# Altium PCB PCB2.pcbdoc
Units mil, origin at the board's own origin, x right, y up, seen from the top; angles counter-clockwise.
Board outline 2219.76 x 1776.53 mil, 4 copper layers (Top Layer, GND, VCC, Bottom Layer), stack 62.447 mil thick; 53 components, 34 nets, 195 pads, 28 vias.
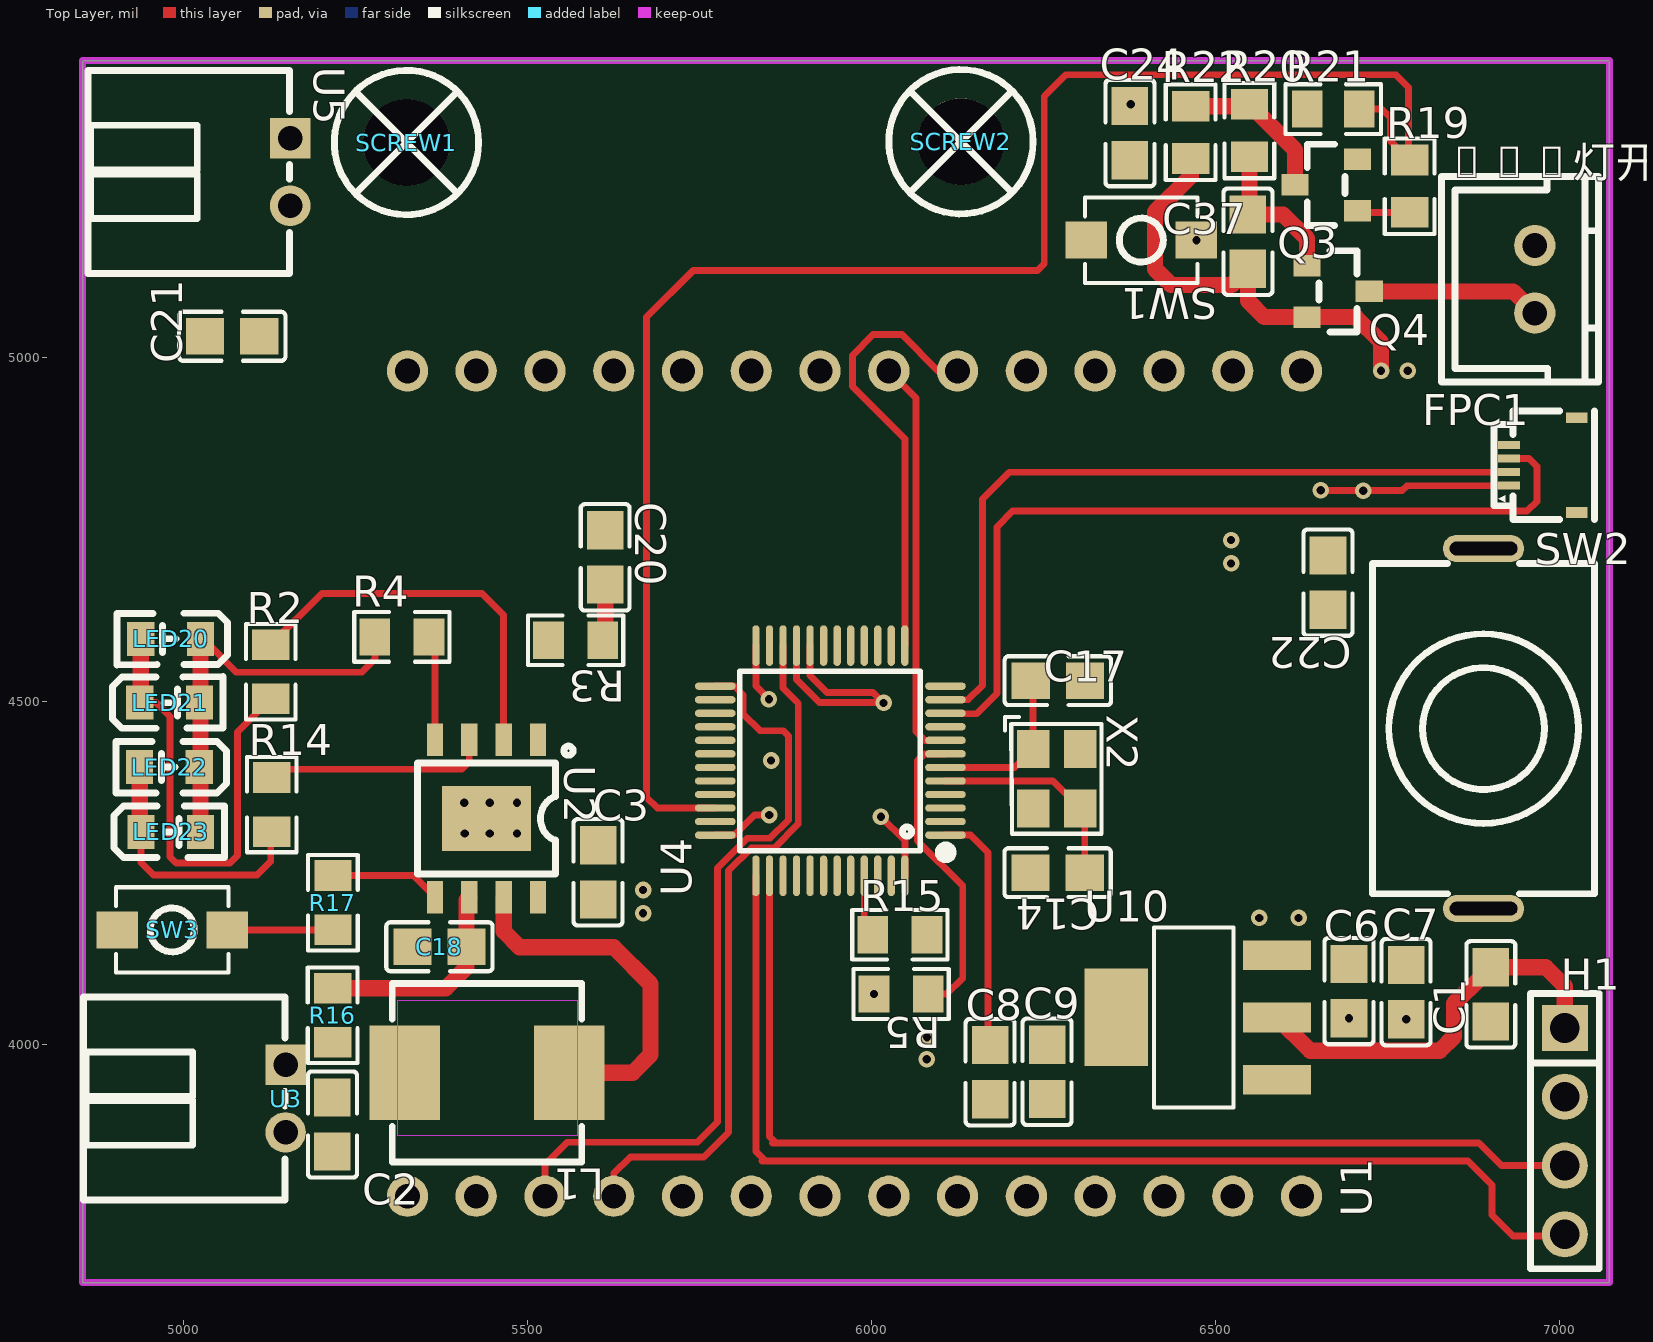
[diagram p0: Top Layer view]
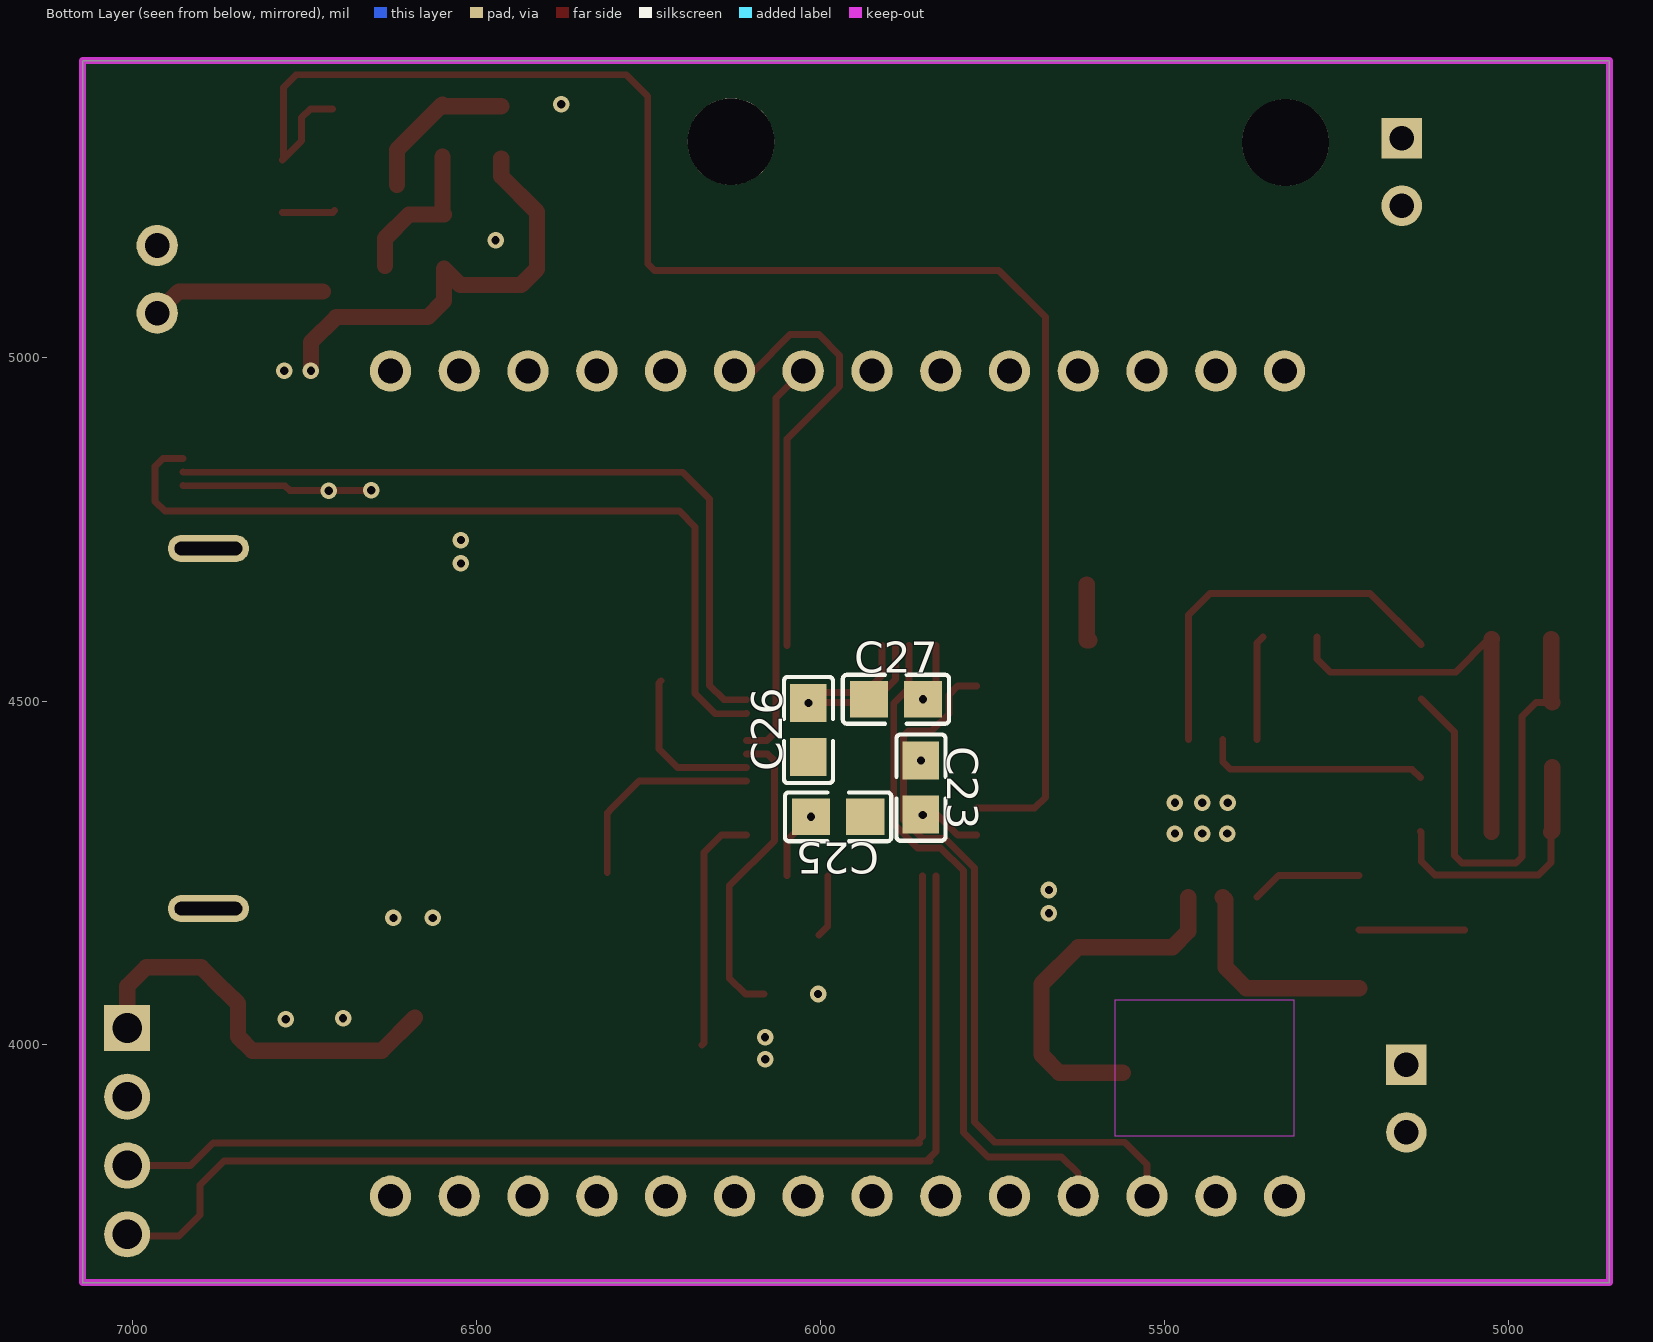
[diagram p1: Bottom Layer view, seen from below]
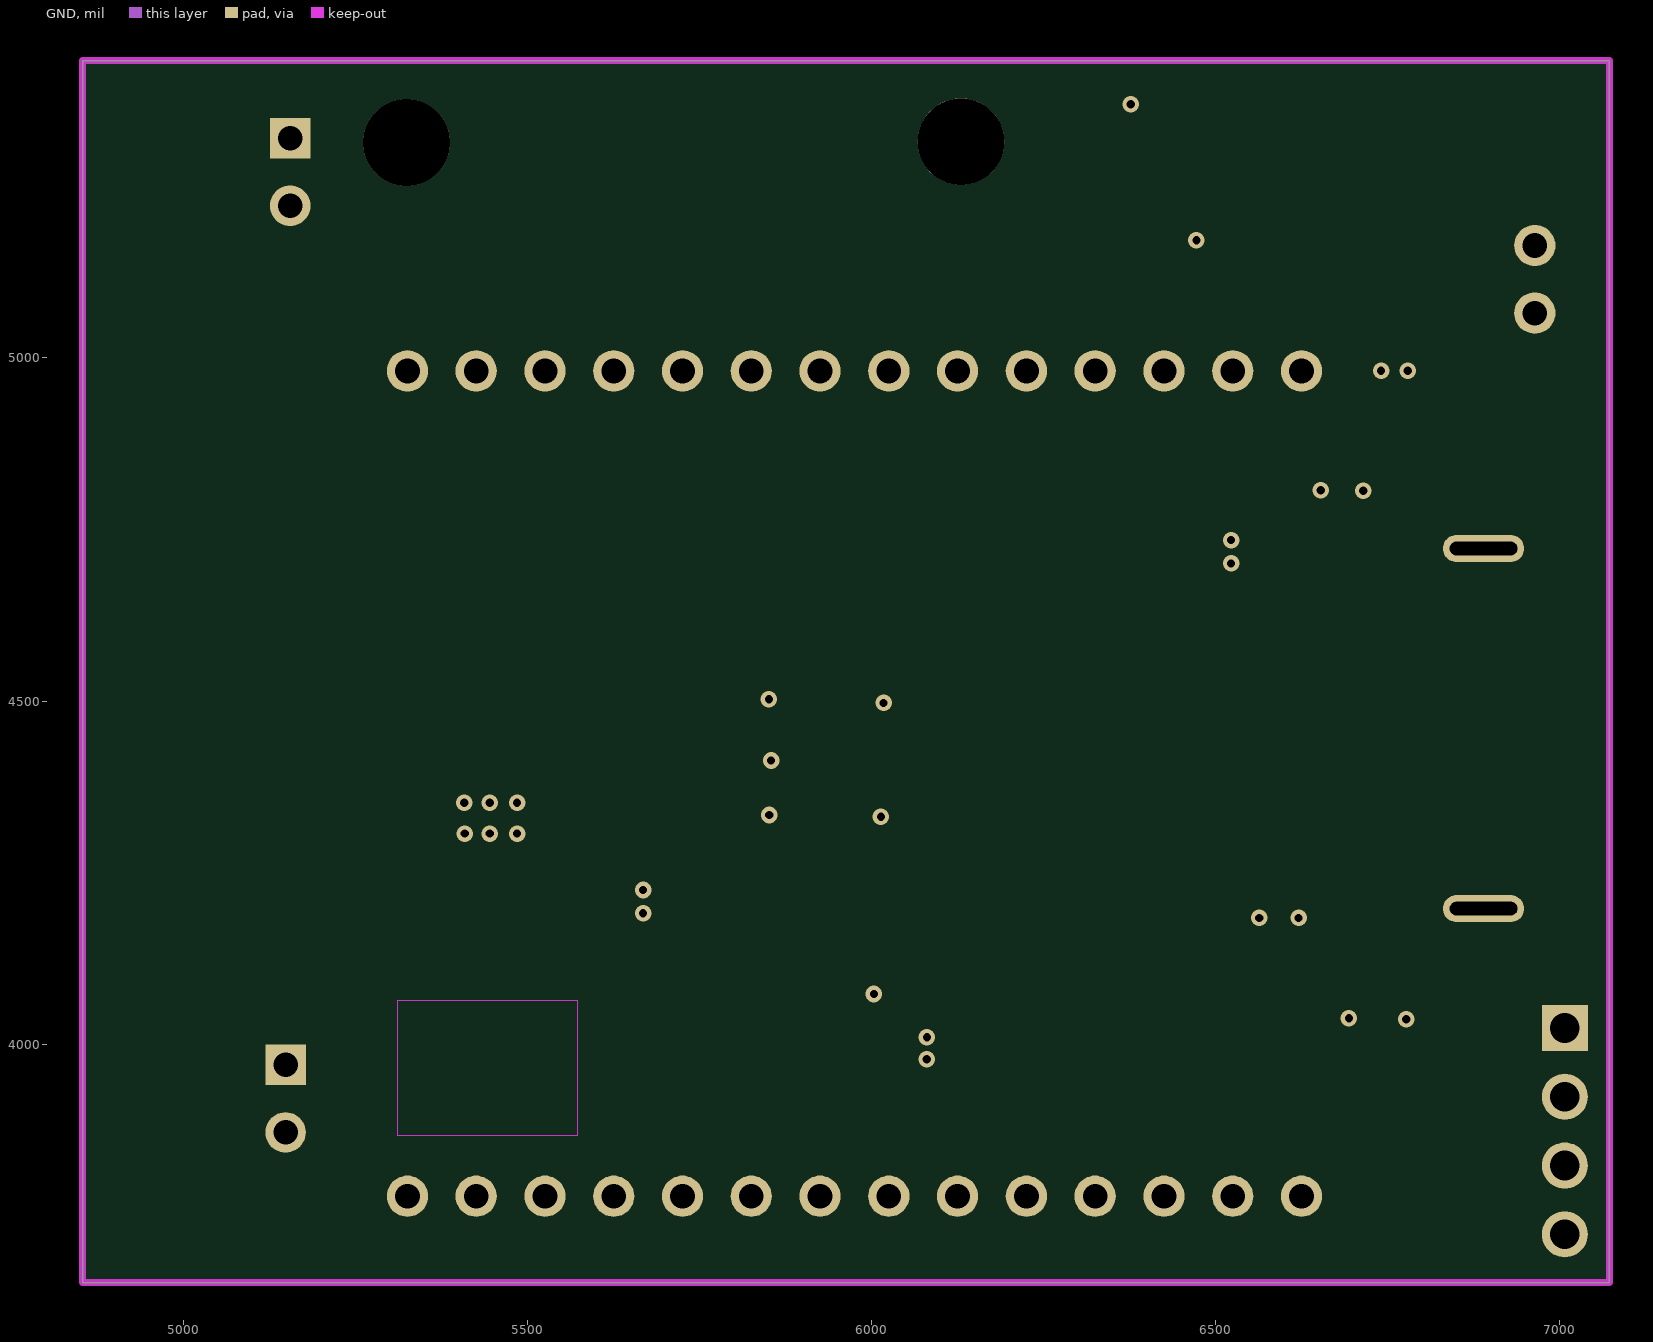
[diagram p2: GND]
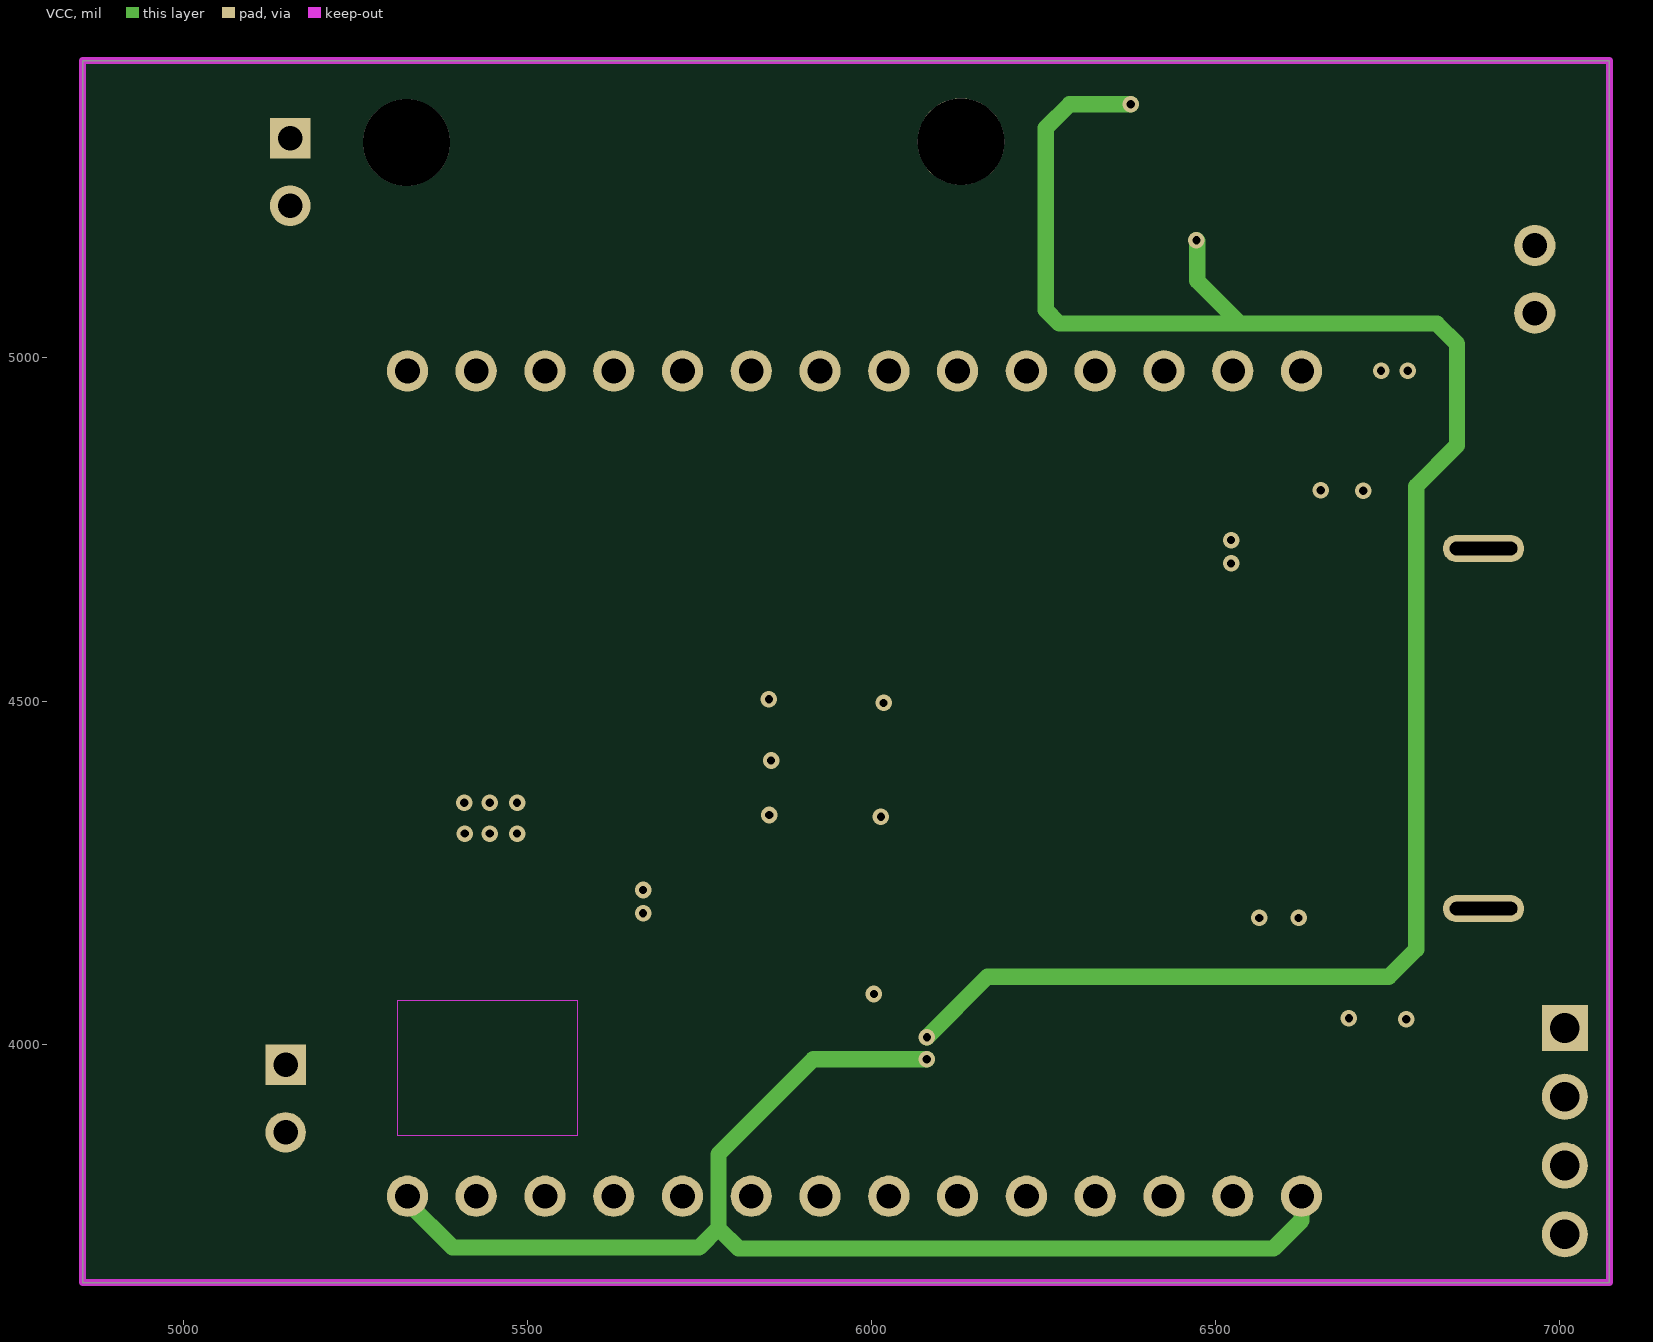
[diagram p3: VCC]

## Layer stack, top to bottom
Top Layer: signal copper 1.378
Dielectric1: surface 8.283, 7628 RC49% 8.6mil, Dk 0
GND: signal copper 0.598
Dielectric2: surface 41.929, 1.1mm H/HOZ Copper, Dk 0
VCC: signal copper 0.598
Dielectric3: surface 8.283, 7628 RC49% 8.6mil, Dk 0
Bottom Layer: signal copper 1.378

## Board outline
4852.85,5431.05 7072.61,5431.05 7072.61,3654.52 4852.85,3654.52

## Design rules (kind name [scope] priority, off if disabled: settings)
BoardOutlineClearance copperThickness1oz [All] p0: genericclearance=10 ignorepadtopadclearanceinfootprint=FALSE except(0: Arc-SplitContinuation Track-SplitContinuation SMDPad-SplitContinuation THPad-SplitContinuation Via-SplitContinuation Fill-SplitContinuation Poly-SplitContinuation Region-SplitContinuation Text-SplitContinuation)
BoardOutlineClearance copperThickness2oz [All] p0: genericclearance=10 ignorepadtopadclearanceinfootprint=FALSE except(0: Arc-SplitContinuation Track-SplitContinuation SMDPad-SplitContinuation THPad-SplitContinuation Via-SplitContinuation Fill-SplitContinuation Poly-SplitContinuation Region-SplitContinuation Text-SplitContinuation)
BoardOutlineClearance otherClearance [All] p0: genericclearance=10 ignorepadtopadclearanceinfootprint=FALSE except(0: Arc-SplitContinuation Track-SplitContinuation SMDPad-SplitContinuation THPad-SplitContinuation Via-SplitContinuation Fill-SplitContinuation Poly-SplitContinuation Region-SplitContinuation Text-SplitContinuation)
Clearance copperThickness1oz [All] p1: gap=7 ignorepadtopadclearanceinfootprint=FALSE
Clearance copperThickness2oz [All] p1: gap=7 ignorepadtopadclearanceinfootprint=FALSE
Clearance otherClearance [All] p1: gap=7 ignorepadtopadclearanceinfootprint=FALSE
DiffPairsRouting differentialPair [All] p1: maxuncoupledlength=10 minlimit=6 maxlimit=Infinity mostfreqgap=6 toplayer_minwidth=5 toplayer_prefwidth=10 toplayer_maxwidth=100 bottomlayer_minwidth=5 bottomlayer_prefwidth=10 bottomlayer_maxwidth=100 midlayer1_minwidth=5 midlayer1_prefwidth=10 midlayer1_maxwidth=100 midlayer2_minwidth=5 midlayer2_prefwidth=10 midlayer2_maxwidth=100
PasteMaskExpansion pasteMaskExpansion [All] p1: expansion=0
PlaneConnect innerPlane [All] p1: planeconnectstyle=Relief reliefexpansion=20 reliefentries=4 reliefconductorwidth=10 reliefairgap=10
PolygonConnect copperRegion [All] p1: connectstyle=Direct reliefentries=4 reliefconductorwidth=10 polygonreliefangle="90 Angle" airgapwidth=10
RoutingVias viaSize [All] p1: viastyle="Through Hole" holewidth=12.0078 minholewidth=11.811 maxholewidth=248.0314 width=12.0078 minwidth=11.811 maxwidth=248.0314
SolderMaskExpansion solderMaskExpansion [IsVia] p1: useseparateexpansions=TRUE expansion=-1000 expansionbottom=-1000
SolderMaskExpansion solderMaskExpansion [All] p2: useseparateexpansions=TRUE expansion=2 expansionbottom=2
Width copperThickness1oz [All] p1: maxlimit=100 minlimit=5 preferedwidth=10
Width copperThickness2oz [All] p1: maxlimit=100 minlimit=8 preferedwidth=10

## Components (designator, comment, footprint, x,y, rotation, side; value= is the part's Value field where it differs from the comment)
C1 "100nF" C0603 6900.29,4073.48 r90 top
C2 "100nF" C0805 5216.06,3884.23 r90 top
C3 "100nF" C0805 5602.23,4250.95 r90 top
C6 "10uF" C0603 6694.05,4078.21 r90 top
C7 "100nF" C0603 6777.14,4076.63 r90 top
C8 "100nF" C0603 6172.31,3960.33 r90 top
C9 "10uF" C0603 6255.1,3960.89 r90 top
C14 "20pF" C0603_2 6270.42,4250.39 r180 top
C17 "20pF" C0603_2 6270.74,4529.52 r0 top
C18 "100nF" C0805 5371.61,4142.71 r0 top
C20 "100nF" C0805 5612.64,4708.87 r270 top
C21 "100nF" C0805 5070.3,5030.31 r180 top
C22 "100nF" C0805 6663.52,4672.17 r270 top
C23 "100nF" C0603 5853.74,4374.14 r270 bottom
C24 "100nF" C0603 6375.59,5325.67 r90 top
C25 "100nF" C0603 5974.19,4331.6 r0 bottom
C26 "100nF" C0603 6017.3,4457.82 r90 bottom
C27 "4.7uF" C0603_1 5890.13,4502.56 r180 bottom
C37 "100nF" C0805 6547.18,5167.82 r270 top
FPC1 "HC-FPC-05-09-4RLTAG" FPC-SMD_4P-P0.50_HC-FPC-05-09-4RLTAG 6975.95,4842.92 r270 top
H1 "" HDR-TH_4P-P2.54-V-M 7007.89,3874.59 r270 top
L1 "10uH" L0805 5440.72,3959.51 r180 top
LED20 "" LED_0805 4978.63,4590.46 r180 top
LED21 "" LED_0805 4981.1,4497.52 r0 top
LED22 "" LED_0805 4977.08,4404.06 r180 top
LED23 "" LED_0805 4982.85,4309.49 r0 top
LED灯开关 "" HDR-TH_2P-P2.54-V-F 6964.24,5113.17 r90 top
Q3 "" S8050_SOT-23 6660.91,5250.45 r0 top
Q4 "" AO3401A_SOT-23-3 6678.23,5095.56 r180 top
R2 "10K" R0805 5126.3,4542.43 r90 top
R3 "10K" R0805 5569.51,4588.43 r180 top
R4 "10K" R0805 5317.1,4593.1 r0 top
R5 "10K" R0603 6042.73,4074 r180 top
R14 "10K" R0805 5127.65,4349.51 r90 top
R15 "10kΩ" R0603 6041.1,4160.05 r0 top
R16 "10K" R0805 5216.31,4042.97 r270 top
R17 "10K" R0805 5216.77,4206.84 r270 top
R19 "1kΩ" ? 6782.34,5248.48 r270 top
R20 "1kΩ" ? 6549.49,5329.42 r270 top
R21 "1kΩ" ? 6671.18,5360.89 r0 top
R22 "1kΩ" ? 6464,5326.88 r270 top
SCREW1 "" M3螺丝 5323.63,5312.02 r0 top
SCREW2 "" M3螺丝 6129.88,5313.25 r0 top
SW1 "" Key_SMD_3x4x2 6392.08,5170.08 r180 top
SW2 "1208SW" SW-TH_L12.0-W8.0-P13.30_YT-1208-YD 6889.75,4459.94 r270 top
SW3 "" Key_SMD_3x4x2 4983.05,4167.14 r180 top
U1 "" 【微雪】ESP32-S3-LCD-1.47B插座封装 6635,4370 r90 top
U2 "IP5306" ESOP-8_L4.9-W3.9-P1.27-LS6.0-BL-EP 5439.97,4329.31 r180 top
U3 "2.54mm-2P WZ" CONN-TH_2P-P2.50_HX-2.54MM-2P-WZ-1 5147.88,3921.95 r270 top
U4 "STM32G431CBT6" LQFP-48_L7.0-W7.0-P0.50-LS9.0-BL_1 5940.01,4413.29 r90 top
U5 "2.54mm-2P WZ" CONN-TH_2P-P2.50_HX-2.54MM-2P-WZ-1 5154.53,5269.25 r270 top
U10 "AMS1117-3.3" SOT-223-3_L6.5-W3.4-P2.30-LS7.0-BR 6472.37,4039.89 r0 top
X2 "8MHz" OSC-SMD_4P-L3.2-W2.5-BL 6269.11,4386.9 r270 top

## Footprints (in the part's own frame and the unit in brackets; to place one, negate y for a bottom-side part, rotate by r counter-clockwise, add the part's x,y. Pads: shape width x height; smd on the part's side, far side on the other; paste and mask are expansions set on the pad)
AO3401A_SOT-23-3 [mm]
  rect 1x0.8 smd paste+0 mask+0.051: 1(1.15,-0.95) 2(1.15,0.95) 3(-1.15,0)
  silkscreen extent -0.7,-1.5 0.7,1.5
C0603 [mm]
  rect 1.41x1.35 smd paste-100 mask+0.051: 1(-1,0) 2(1,0)
  silkscreen extent -1.96,-0.9 1.96,0.9
C0603_1 [mm]
  rect 1.41x1.35 smd paste-100 mask+0.051: 1(-1,0) 2(1,0)
  silkscreen extent -1.96,-0.9 1.96,0.9
C0603_2 [mm]
  rect 1.41x1.35 smd paste-100 mask+0.051: 1(-1,0) 2(1,0)
  silkscreen extent -1.96,-0.9 1.96,0.9
C0805 [mm]
  rect 1.41x1.35 smd paste-100 mask+0.051: 1(-1,0) 2(1,0)
  silkscreen extent -1.96,-0.9 1.96,0.9
CONN-TH_2P-P2.50_HX-2.54MM-2P-WZ-1 [mm]
  rect 1.5x1.5 hole 0.9 paste+0 mask+0.05: 1(-1.25,0)
  round 1.5 hole 0.9 paste+0 mask+0.05: 2(1.25,0)
  silkscreen extent -3.75,-7.46 3.75,-0.02
ESOP-8_L4.9-W3.9-P1.27-LS6.0-BL-EP [mm]
  rect 0.6x1.2 smd: 1(-1.905,-2.908) 2(-0.635,-2.908) 3(0.635,-2.908) 4(1.905,-2.908) 5(1.905,2.908) 6(0.635,2.908) 7(-0.635,2.908) 8(-1.905,2.908)
  rect 3.3x2.4 smd: 9(0,0)
  silkscreen extent -3.2,-2.67 2.55,2.05
FPC-SMD_4P-P0.50_HC-FPC-05-09-4RLTAG [mm]
  rect 0.3x0.8 smd paste+0 mask+0.05: 1(0.75,-1.25) 2(0.25,-1.25) 3(-0.25,-1.25) 4(-0.75,-1.25)
  rect 0.4x0.8 smd paste+0 mask+0.05: 5(-1.75,1.25) 6(1.75,1.25)
  silkscreen extent -2,-1.8 2,1.91
HDR-TH_2P-P2.54-V-F [mil]
  round 60 hole 36: 1(-49.21,0) 2(49.21,0)
  silkscreen extent -150,-93 150,136
HDR-TH_4P-P2.54-V-M [mm]
  rect 1.7x1.7 hole 1.1: 1(-3.81,0)
  round 1.7 hole 1.1: 2(-1.27,0) 3(1.27,0) 4(3.81,0)
  silkscreen extent -5.08,-1.27 5.08,1.27
Key_SMD_3x4x2 [mm]
  rect 1.53x1.36 smd paste+0 mask+0.051: 1(-2.035,0) 2(2.035,0)
  silkscreen extent -2.08,-1.58 2.08,1.58
L0805 [mm]
  rect 2.6x3.5 smd: 1(-3.035,0) 2(3.035,0)
  silkscreen extent -3.5,-3.3 3.5,3.3
LED_0805 [mm]
  rect 1x1.25 smd paste+0 mask+0.051: 1(-1.15,0.005) 2(1.05,0.005)
  silkscreen extent -2.15,-0.94 1.93,0.97
LQFP-48_L7.0-W7.0-P0.50-LS9.0-BL_1 [mm]
  oval 0.27x1.5 smd paste+0 mask+0.05: 1(-2.75,-4.25) 2(-2.25,-4.25) 3(-1.75,-4.25) 4(-1.25,-4.25) 5(-0.75,-4.25) 6(-0.25,-4.25) 7(0.25,-4.25) 8(0.75,-4.25) 9(1.25,-4.25) 10(1.75,-4.25) 11(2.25,-4.25) 12(2.75,-4.25) 25(2.75,4.25) 26(2.25,4.25) 27(1.75,4.25) 28(1.25,4.25) 29(0.75,4.25) 30(0.25,4.25) 31(-0.25,4.25) 32(-0.75,4.25) 33(-1.25,4.25) 34(-1.75,4.25) 35(-2.25,4.25) 36(-2.75,4.25)
  oval 1.5x0.27 smd paste+0 mask+0.05: 13(4.25,-2.75) 14(4.25,-2.25) 15(4.25,-1.75) 16(4.25,-1.25) 17(4.25,-0.75) 18(4.25,-0.25) 19(4.25,0.25) 20(4.25,0.75) 21(4.25,1.25) 22(4.25,1.75) 23(4.25,2.25) 24(4.25,2.75) 37(-4.25,2.75) 38(-4.25,2.25) 39(-4.25,1.75) 40(-4.25,1.25) 41(-4.25,0.75) 42(-4.25,0.25) 43(-4.25,-0.25) 44(-4.25,-0.75) 45(-4.25,-1.25) 46(-4.25,-1.75) 47(-4.25,-2.25) 48(-4.25,-2.75)
  silkscreen extent -3.59,-4.46 3.3,3.34
M3螺丝 [mil]
  round 126 hole 126 paste+0 mask+4: 1(0,0)
  silkscreen extent -105,-105 105,105
OSC-SMD_4P-L3.2-W2.5-BL [mm]
  rect 1.4x1.2 smd paste+0 mask+0.051: 1(-1.1,-0.875) 2(1.1,-0.875) 3(1.1,0.875) 4(-1.1,0.875)
  silkscreen extent -2.29,-1.9 2.03,1.65
R0603 [mm]
  rect 1.133x1.377 smd paste-100 mask+0.051: 1(-1,0) 2(1,0)
  silkscreen extent -1.76,-0.92 1.76,0.92
R0805 [mm]
  rect 1.133x1.377 smd paste-100 mask+0.051: 1(-1,0) 2(1,0)
  silkscreen extent -1.76,-0.92 1.76,0.92
S8050_SOT-23 [mm]
  rect 1x0.8 smd paste+0 mask+0.051: 1(1.15,-0.95) 2(1.15,0.95) 3(-1.15,0)
  silkscreen extent -0.7,-1.5 0.7,1.5
SOT-223-3_L6.5-W3.4-P2.30-LS7.0-BR [mm]
  rect 2.5x1.1 smd: 1(2.97,-2.3) 2(2.97,0) 3(2.97,2.3)
  rect 2.34x3.6 smd: 4(-2.97,0)
  silkscreen extent -1.57,-3.33 1.37,3.33
SW-TH_L12.0-W8.0-P13.30_YT-1208-YD [mm]
  oval 1x3 hole 0.5 slot 2.5 at 90 deg: 1(-6.65,0) 2(6.65,0)
  silkscreen extent -6.1,-4.1 6.1,4.1
【微雪】ESP32-S3-LCD-1.47B插座封装 [mil]
  round 60 hole 36: 1(-590,1310) 2(-590,1210) 3(-590,1110) 4(-590,1010) 5(-590,910) 6(-590,810) 7(-590,710) 8(-590,610) 9(-590,510) 10(-590,410) 11(-590,310) 12(-590,210) 13(-590,110) 14(-590,10) 15(610,1310) 16(610,1210) 17(610,1110) 18(610,1010) 19(610,910) 20(610,810) 21(610,710) 22(610,610) 23(610,510) 24(610,410) 25(610,310) 26(610,210) 27(610,110) 28(610,10)
? [mil]
  rect 44.59x54.21 smd: 1(-38.04,0) 2(38.04,0)
  silkscreen extent -69,-36 69,36

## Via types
v1: diameter 24.02, hole 12.01, Top Layer to Bottom Layer, 28 vias

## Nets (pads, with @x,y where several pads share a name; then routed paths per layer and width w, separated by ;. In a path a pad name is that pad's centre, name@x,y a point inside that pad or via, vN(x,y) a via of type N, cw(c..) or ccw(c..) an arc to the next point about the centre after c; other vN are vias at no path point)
3V3: C1.2 C8.2 C9.2 C23.2 C24.2 C25.2 C26.2 C27.2 H1.1 R5.2 SW1.1 U1.1 U1.14 U4.1 U4.20 U4.21 U4.24 U4.36 U4.48 U10.2 U10.4 | length 6292.9
  Top Layer w10: U4.36 5800.26,4305.02 5829.49,4334.26 v1(5851.16,4334.26) ; U4.24 5831.74,4521.58 v1(5850.76,4502.56) ; U4.21 5890.8,4531.42 5924.32,4497.9 v1@6016.6,4497.9 ; U4.20 5910.48,4537.37 5935.34,4512.5 6001.99,4512.5 v1@6016.6,4497.9 ; v1(6013.56,4331.6) 6048.28,4296.89 U4.48 ; v1(6017.3,4497.19) v1@6016.6,4497.9 ; U4.1 6143.84,4305.02 6169.31,4279.55 6169.31,4002.71 C8.2
  Top Layer w23.62: U10.2 6637.71,3991.48 6826.06,3991.48 6846.82,4012.24 6846.82,4060.13 6866.34,4079.66 6867.1,4079.66 C1.2 6980.33,4112.85 7007.89,4085.29 H1.1
  VCC w23.62: U1.1 5325,3771.02 5390.7,3705.32 5749.17,3705.32 5777.2,3733.35 ; v1(6080.26,3979.1) 5915.24,3979.1 5777.2,3841.06 5777.2,3733.35 ; v1(6080.45,4011.1) 6168.33,4098.98 6751.84,4098.98 6791.73,4138.88 6791.73,4812.26 6851.09,4871.62 6851.09,5019.53 6821.9,5048.72 6535.81,5048.72 ; v1(6376.89,5367.7) 6287.8,5367.7 6253.2,5333.1 6253.2,5068.42 6272.9,5048.72 6535.81,5048.72 ; v1(6472.2,5170.08) 6473.53,5168.75 6473.53,5111 6535.81,5048.72 ; U1.14 6625,3744.65 6584.37,3704.02 5806.54,3704.02 5777.2,3733.35
  other v1: 6003.36,4074
$1N80: R15.1 U4.45 | length 91.1
  Top Layer w10: U4.45 5989.22,4172.56 R15.1
$1N109: R17.1 U2.5 | length 161.2
  Top Layer w10: R17.1 5333.57,4246.21 U2.5
$1N110: R17.2 SW3.1 | length 153.7
  Top Layer w10: SW3.1 5216.43,4167.14 R17.2
$1N111: C18.2 R16.1 U2.6 | length 311
  Top Layer w23.62: R16.1 5216.44,4082.48 5380.81,4082.48 5410.98,4112.65 C18.2 5410.98,4210.82 U2.6
$1N114: L1.1 U2.7 | length 527.1
  Top Layer w23.62: U2.7 5464.97,4165.07 5487.95,4142.1 5624.98,4142.1 5678.49,4088.58 5678.49,3985.51 5652.5,3959.51 L1.1
$1N117: R4.2 U2.4 | length 152.8
  Top Layer w10: R4.2 5364.97,4584.6 U2.4
$1N118: R14.2 U2.3 | length 328.7
  Top Layer w10: R14.2 5139.47,4400.69 5403.65,4400.69 5414.97,4412.02 U2.3
$1N119: LED22.2 LED23.1 R14.1 | length 388.2
  Top Layer w10: LED23.1 4937.57,4265.3 4956.1,4246.76 5106.64,4246.76 5126.3,4266.43 5126.3,4308.79 R14.1
  Top Layer w23.62: LED22.2 4935.74,4311.52 LED23.1
$1N120: LED20.1 LED21.2 LED22.1 LED23.2 R4.1 | length 594.7
  Top Layer w10: LED20.1 5028.29,4590.26 5076.8,4541.74 5258.53,4541.74 5277.73,4560.94 R4.1
  Top Layer w23.62: LED20.1 5024.19,4589.98 LED23.2
$1N121: R2.2 U2.2 | length 563.7
  Top Layer w10: R2.2 5200.87,4656.37 5433.46,4656.37 5464.97,4624.86 U2.2
$1N122: LED20.2 LED21.1 R2.1 | length 703.7
  Top Layer w10: LED21.1 4959.64,4497.73 4979.86,4477.51 4979.86,4273.47 4988.9,4264.43 5067.06,4264.43 5077.91,4275.28 5077.91,4454.67 R2.1
  Top Layer w23.62: LED21.1 4937.29,4499.2 LED20.2
$1N125: C20.2 R3.1 | length 84.8
  Top Layer w23.62: R3.1 5612.64,4588.43 C20.2
$1N135: LED灯开关.1 Q4.3 | length 253.8
  Top Layer w23.62: Q4.3 6932.64,5095.56 LED灯开关.1
$1N136: C37.1 Q4.1 R20.2 | length 224.8
  Top Layer w23.62: R20.2 6549.49,5209.5 C37.1 6598.25,5207.19 6632.96,5172.48 Q4.1
$1N138: Q3.3 R20.1 R22.1 | length 230.9
  Top Layer w23.62: R22.1 6546.95,5364.92 R20.1 6615.64,5301.31 Q3.3
$1N140: Q3.1 R19.2 | length 77.2
  Top Layer w10: Q3.1 6708.8,5210.44 R19.2
+5V: C6.2 C7.2 C37.2 FPC1.1 Q4.2 R22.2 SW2.2 U1.15 U10.3 | length 920.1
  Top Layer w10: v1(6652.84,4806.34) 6771.49,4806.34 6778.1,4812.95 6926.29,4812.95 FPC1.1
  Top Layer w23.62: R22.2 6464,5263.11 6411.92,5211.03 6411.92,5128.18 6435.28,5104.83 6523.55,5104.83 C37.2 6547.18,5081.83 6570.85,5058.16 Q4.2 6704.06,5058.16 6740.71,5021.5 v1(6740.71,4980.27)
  other v1: 6563.63,4184.67 6620.72,4184.67 6714.64,4805.84 6779.54,4980.27
BAT: C2.2 L1.2 R16.2 U3.1
DATA_RDY: U1.23 U4.13 | length 640.8
  Top Layer w10: U4.13 6048.54,4580.87 6048.54,4881.27 5972.19,4957.62 5972.19,5002.63 6002.19,5032.64 6043.9,5032.64 6096.53,4980 U1.23
GND: C1.1 C2.1 C3.2 C6.1 C7.1 C8.1 C9.1 C14.2 C17.2 C18.1 C20.1 C21.1 C22.2 C23.1 C24.1 C25.1 C26.1 C27.1 FPC1.4 H1.2 LED灯开关.2 Q3.2 R15.2 R21.1 SCREW1.1 SCREW2.1 SW1.2 SW3.2 U1.2 U1.13 U1.16 U2.9 U3.2 U4.19 U4.23 U4.35 U4.47 U5.1 U10.1 X2.2 X2.4
  other v1: 6777.14,4037.26 6694.05,4038.84 5408.31,4307.23 5444.64,4307.23 5484.43,4307.23 5407.74,4352.21 5444.64,4352.21 5484.43,4352.21 5853.74,4413.51
OSC_IN: C14.1 U4.5 X2.3 | length 308.7
  Top Layer w10: U4.5 6263.39,4383.76 X2.3 6309.79,4337.36 C14.1
OSC_OUT: C17.1 U4.6 X2.1 | length 239.1
  Top Layer w10: U4.6 6207.9,4403.45 X2.1 6234.66,4526.23 C17.1
PA12: R19.1 R21.2 U4.34 | length 2436.3
  Top Layer w10: U4.34 5688.32,4344.39 5672.78,4359.93 5672.78,5058.17 5740.63,5126.02 6241,5126.02 6251,5136.02 6251,5379.31 6282.19,5410.5 6762.47,5410.5 6780.78,5392.19 R19.1@6780.78,5288.08 ; R21.2 6741.56,5360.89 6754.34,5348.11 6754.34,5314.53 R19.1@6780.78,5288.08 ; R19.1 R19.1@6780.78,5288.08
RESET: R5.1 U4.7 | length 447.6
  Top Layer w10: R5.1 6108.99,4074 6132.5,4097.51 6132.5,4231.1 6066.82,4296.79 6066.82,4413.13 6076.82,4423.13 U4.7
SWCLK: H1.3 U4.38 | length 1558.1
  Top Layer w10: U4.38 5851.43,3866.83 5860.87,3857.39 ; 5855.87,3857.39 5860.87,3857.39 ; H1.3 6915.58,3824.59 6882.78,3857.39 5860.87,3857.39
SWDIO: H1.4 U4.37 | length 1659.9
  Top Layer w10: U4.37 5831.74,3845.14 5845.61,3831.27 ; 5840.61,3831.27 5845.61,3831.27 ; H1.4 7005.17,3721.88 6932.6,3721.88 6901.85,3752.63 6901.85,3796.56 6867.14,3831.27 5845.61,3831.27
UART3_RX: U1.3 U4.25 | length 1098.8
  Top Layer w10: U1.3 5525,3825.91 5557.59,3858.51 5746.79,3858.51 5776,3887.72 5776,4257.32 5819.18,4300.5 5852.52,4300.5 5879.24,4327.22 5879.24,4448.92 5871.38,4456.78 5837.48,4456.78 5813.2,4481.05 5813.2,4508.63 5800.26,4521.56 U4.25
UART3_TX: U1.4 U4.22 | length 1003.2
  Top Layer w10: U1.4 5625,3813.01 5649.14,3837.15 5755.94,3837.15 5791.75,3872.96 5791.75,4253.25 5824.99,4286.49 5858.63,4286.49 5893.25,4321.11 5893.25,4496.76 5871.11,4518.91 U4.22
USART2_RX: FPC1.2 U4.11 | length 1115.4
  Top Layer w10: U4.11 6140.41,4501.87 6161.04,4522.51 6161.04,4793.58 6200.01,4832.55 6926.2,4832.55 FPC1.2
USART2_TX: FPC1.3 U4.10 | length 1226.5
  Top Layer w10: U4.10 6108.11,4481.41 6152.66,4481.41 6182.05,4510.79 6182.05,4753.22 6204.97,4776.13 6953.13,4776.13 6967.23,4790.24 6967.23,4841.27 6955.74,4852.76 FPC1.3
VIN_5V: C21.2 R3.2 U2.1 U5.2
VOUT_5V: C3.1 C22.1 SW2.1 U2.8
  other v1: 5667.64,4191.3 5667.64,4225.2 6522.61,4700.05 6522.61,4733.95
WAKE: U1.22 U4.8 | length 588.8
  Top Layer w10: U1.22 6064.58,4940.42 6064.58,4455.73 6077.49,4442.82 U4.8
pads on no net: FPC1.5 FPC1.6 U1.5 U1.6 U1.7 U1.8 U1.9 U1.10 U1.11 U1.12 U1.17 U1.18 U1.19 U1.20 U1.21 U1.24 U1.25 U1.26 U1.27 U1.28 U4.2 U4.3 U4.4 U4.9 U4.12 U4.14 U4.15 U4.16 U4.17 U4.18 U4.26 U4.27 U4.28 U4.29 U4.30 U4.31 U4.32 U4.33 U4.39 U4.40 U4.41 U4.42 U4.43 U4.44 U4.46

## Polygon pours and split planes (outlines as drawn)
BAT on Top Layer (solid, remove dead copper, pour order 0): 5075.13,3965.17 5093.55,3965.17 5155.59,4027.21 5374.28,4027.21 5374.28,3907.65 5075.13,3907.65
VIN_5V on Top Layer (solid, remove dead copper, pour order 2): 5554.27,4487.69 5557.66,4440.65 5557.66,4419.88 5554.27,4416.49 5500.7,4416.49 5493.94,4423.25 5493.94,4638.63 5451.9,4680.68 5032.15,4680.68 4965.01,4747.81 4965.01,5222.48 4966.37,5223.84 5063.34,5223.84 5063.34,4806.13 5129.12,4740.35 5524.45,4740.35 5561.07,4703.73
VOUT_5V on Top Layer (solid, remove dead copper, pour order 6): 5498.62,4240.97 5500.65,4243 5684.42,4243 5693.23,4234.19 5693.23,4182.65 5685.1,4174.51 5512.86,4174.51 5498.62,4188.75
3V3 on Top Layer (solid, remove dead copper, pour order 14): 6404.72,4114.23 6404.72,3965.45 6139.08,3965.45 6132.54,3971.98 6132.54,4029.27 6141.38,4038.11 6286.7,4038.11 6297.08,4048.49 6297.08,4114.61 6404.34,4114.61
3V3 on Top Layer (solid, remove dead copper, pour order 18): 6308.26,4111.71 6489.04,4111.71 6540.94,4059.81 6637.82,4059.81 6637.82,4017.43 6538.35,4017.43 6489.91,3968.99 6308.26,3968.99
VOUT_5V on Top Layer (solid, remove dead copper, pour order 4): 6954.22,4752.9 6954.22,4674.57 6492.09,4674.57 6492.09,4754.25 6952.87,4754.25
+5V on Top Layer (solid, remove dead copper, pour order 10): 6962.96,4240.21 6962.96,4154.89 6859.57,4155.2 6859.57,4087.75 6549.73,4087.75 6533.46,4104.03 6533.46,4146.75 6541.59,4154.89 6742.99,4154.89 6742.99,4261.35 6783.21,4276.54 6939.77,4276.54
+5V on VCC (solid, remove dead copper): 6736.35,4901.23 6736.35,4776.54 6735.95,4776.13 5408.27,4776.13 5286.63,4897.77 5286.63,5036.17 5302.2,5051.74 5369.67,5051.74 5380.05,5041.36 5380.05,4936.7 5472.6,4844.14 6643.56,4844.14 6700.65,4901.23
VOUT_5V on VCC (solid, remove dead copper): 5634.38,4170.72 5634.38,4662.46 5727.8,4755.88 6585.42,4755.88 6599.69,4741.61 6599.69,4687.11 6591.91,4679.33 5806.94,4679.33 5709.63,4582.02 5709.63,4168.13 5700.55,4159.04 5646.06,4159.04
+5V on VCC (solid, remove dead copper): 6536.11,4219 6536.11,4590.94 6622.61,4677.44 6622.61,4832.55 6647.41,4857.35 6729,4857.35 6741.11,4845.24 6741.11,4604.78 6645.96,4509.63 6645.96,4164.51 6639.91,4158.45 6546.49,4158.45 6536.11,4168.83
+5V on VCC (solid, remove dead copper): 6624.32,4832.55 6707.36,4915.58 6707.36,5009.15 6808.56,5009.15 6808.56,4905.21 6735.91,4832.55
VIN_5V on Top Layer (solid, remove dead copper, pour order 20): 4966.67,5260.05 5211.89,5260.05 5211.89,5176.37 4966.67,5176.37
GND on Top Layer (solid, remove dead copper, pour order 22): 4665.88,5590.21 7398.33,5590.21 7398.33,3457.66 4665.88,3457.66
GND on GND (solid, remove dead copper): 4650.63,5695.68 7391.85,5695.68 7391.85,3405.49 4650.63,3405.49
GND on Bottom Layer (solid, remove dead copper, pour order 22): 4411.93,5743.2 7684.46,5743.2 7684.46,3340.62 4411.93,3340.62
3V3 on Top Layer (solid, remove dead copper, pour order 16): 6066.03,4034.46 6183.09,4034.46 6183.09,3965.83 6066.03,3965.83
+5V on Top Layer (solid, remove dead copper, pour order 12): 6533.36,4221.86 6648.4,4221.86 6648.4,4089.52 6533.36,4089.52
3V3 on VCC (solid, remove dead copper): 5804.94,4545.66 6125.84,4545.66 6125.84,3965.26 5804.94,3965.26

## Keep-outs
Board Outline Layer:
  region: 5311.3,4064.64 5571.84,4064.64 5571.84,3867.77 5311.3,3867.77
  lines w10: 4852.85,3654.52 7072.61,3654.52 7072.61,5431.05 4852.85,5431.05 4852.85,3654.52

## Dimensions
5230,3780 to 5230,4980 on Document Layer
